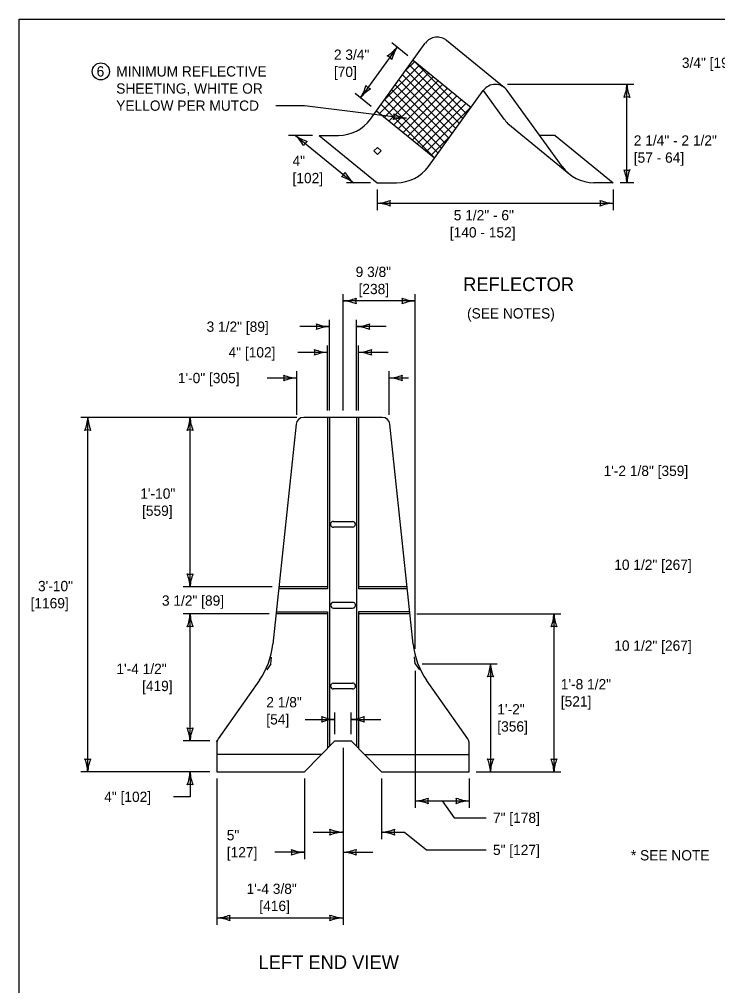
# Model space of a CAD drawing. Extents: x 49991.4 to 50021, y 49987.6 to 50011.4.
# Drawn here: x 49999.38 to 50003.46, y 49993.36 to 49999 of the extents above; entities that cross this region are included whole.
import ezdxf

# ---------------------------------------------------------------- set-up
doc = ezdxf.new("R2010")
doc.units = 0
for name, color, linetype in [('Level 1', 7, 'Continuous'), ('Level 2', 7, 'Continuous'), ('Level 3', 7, 'Continuous'), ('Level 4', 7, 'Continuous')]:
    doc.layers.add(name, color=color, linetype=linetype)

msp = doc.modelspace()

# ---------------------------------------------------------------- linework, layer by layer
at = {"layer": 'Level 1'}
for p, q in [((50002.218, 49998.5996), (50001.8793, 49998.8758)), ((50001.434, 49998.4163), (50001.7548, 49998.8598)), ((50001.6829, 49998.7604), (50001.9954, 49998.4479)), ((50001.6834, 49998.7611), (50002.0221, 49998.4849)), ((50001.4886, 49998.4503), (50001.7473, 49998.709)), ((50001.5094, 49998.5206), (50001.7201, 49998.7312)), ((50001.6389, 49998.6995), (50001.6928, 49998.7535)), ((50001.6413, 49998.7029), (50001.9538, 49998.3905)), ((50001.6621, 49998.7317), (50001.9746, 49998.4192)), ((50001.5159, 49998.428), (50001.7746, 49998.6868)), ((50001.5431, 49998.4058), (50001.8019, 49998.6645)), ((50001.5998, 49998.6455), (50001.9123, 49998.333)), ((50001.6206, 49998.6742), (50001.933, 49998.3617)), ((50001.5582, 49998.588), (50001.8707, 49998.2756)), ((50001.5704, 49998.3835), (50001.8291, 49998.6423)), ((50001.579, 49998.6168), (50001.8915, 49998.3043)), ((50001.5976, 49998.3613), (50001.8564, 49998.6201)), ((50001.6249, 49998.3391), (50001.8836, 49998.5978)), ((50001.5167, 49998.5306), (50001.8291, 49998.2181)), ((50001.5375, 49998.5593), (50001.8499, 49998.2469)), ((50001.6522, 49998.3168), (50001.9109, 49998.5756)), ((50001.6794, 49998.2946), (50001.9382, 49998.5533)), ((50001.7067, 49998.2724), (50001.9654, 49998.5311)), ((50001.7727, 49998.1401), (50002.0935, 49998.5835)), ((50002.2151, 49998.4163), (50002.0938, 49998.584)), ((50002.5538, 49998.1401), (50002.233, 49998.5835)), ((50001.4959, 49998.5019), (50001.8084, 49998.1894)), ((50001.734, 49998.2501), (50001.9927, 49998.5089)), ((50001.7612, 49998.2279), (50002.02, 49998.4866)), ((50001.4697, 49998.4657), (50001.8084, 49998.1894)), ((50002.2376, 49998.3898), (50002.6039, 49998.0896)), ((50001.1356, 49998.3213), (50001.2479, 49998.3213)), ((50001.1356, 49998.3213), (50001.4743, 49998.045)), ((50001.7885, 49998.2057), (50001.9029, 49998.3201)), ((50002.5135, 49998.3213), (50002.4227, 49998.3213)), ((50002.5135, 49998.3213), (50002.8522, 49998.045)), ((50001.4743, 49998.045), (50001.5866, 49998.045)), ((50002.8522, 49998.045), (50002.7399, 49998.045)), ((50001.5035, 49996.6742), (50001.0445, 49996.6742)), ((50001.184, 49996.6742), (50001.184, 49995.6732)), ((50001.1952, 49996.6742), (50001.1952, 49994.7528)), ((50001.3527, 49996.6742), (50001.3527, 49994.7528)), ((50001.364, 49996.6742), (50001.364, 49995.6732)), ((50000.9997, 49996.6339), (50000.8643, 49995.3498)), ((50001.6837, 49995.3498), (50001.5482, 49996.6339)), ((50001.2178, 49996.0665), (50001.3303, 49996.0665)), ((50001.3303, 49996.0332), (50001.2178, 49996.0332)), ((50001.184, 49995.6732), (50000.8984, 49995.6732)), ((50001.184, 49995.6844), (50000.8996, 49995.6844)), ((50001.6484, 49995.6844), (50001.364, 49995.6844)), ((50001.6496, 49995.6732), (50001.364, 49995.6732)), ((50000.8842, 49995.5382), (50001.184, 49995.5382)), ((50001.184, 49995.5382), (50001.184, 49994.7413)), ((50001.3303, 49995.594), (50001.2178, 49995.594)), ((50001.2178, 49995.5607), (50001.3303, 49995.5607)), ((50001.6638, 49995.5382), (50001.3642, 49995.5382)), ((50001.3642, 49995.5382), (50001.3642, 49994.7412)), ((50001.184, 49995.5269), (50000.883, 49995.5269)), ((50001.665, 49995.5268), (50001.3642, 49995.5268)), ((50000.7854, 49995.1389), (50000.5452, 49994.7958)), ((50001.2178, 49995.1215), (50001.3303, 49995.1215)), ((50001.3303, 49995.0884), (50001.2178, 49995.0884)), ((50002.0027, 49994.7958), (50001.7625, 49995.1389)), ((50000.5371, 49994.77), (50000.5371, 49994.6042)), ((50001.2262, 49994.7842), (50001.049, 49994.6042)), ((50001.2262, 49994.7842), (50001.3218, 49994.7842)), ((50001.3218, 49994.7842), (50001.499, 49994.6042)), ((50002.0109, 49994.6042), (50002.0109, 49994.77)), ((50000.5371, 49994.6042), (50001.049, 49994.6042)), ((50001.499, 49994.6042), (50002.0109, 49994.6042))]:
    msp.add_line(p, q, dxfattribs=at)
for points in [[(49999.3835, 49998.9992), (50016.7501, 49998.9992), (50016.7501, 49987.7988), (49999.3835, 49987.7988)], [(50001.4546, 49998.2302), (50001.4752, 49998.2095), (50001.4959, 49998.2302), (50001.4752, 49998.2508)]]:
    msp.add_lwpolyline(points, close=True, dxfattribs=at)
for centre, radius, start, end in [((50001.8246, 49998.8093), 0.0861, 50.5461, 144.119), ((50002.1632, 49998.5331), 0.0861, 35.881, 144.119), ((50001.2479, 49998.5509), 0.2297, 270, 324.119), ((50002.4012, 49998.5509), 0.2297, 215.881, 224.5527), ((50001.5866, 49998.2747), 0.2297, 270, 324.119), ((50002.7399, 49998.2747), 0.2297, 215.881, 270), ((50001.2177, 49996.0498), 0.0167, 89.8218, 270.1782), ((50001.3302, 49996.0498), 0.0167, 270.3209, 89.6791), ((50001.2178, 49995.5773), 0.0167, 90.1117, 269.8883), ((50001.3303, 49995.5773), 0.0167, 269.9135, 90.0865), ((50001.2178, 49995.1049), 0.0166, 90.0425, 269.9575), ((50001.3303, 49995.1049), 0.0166, 269.9732, 90.0268)]:
    msp.add_arc(centre, radius, start, end, dxfattribs=at)
for centre, major_axis, start_param, end_param in [((50001.0445, 49996.6292), (-0.045, 0), 4.712389, 6.178105), ((50001.5035, 49996.6292), (-0.045, 0), 3.246673, 4.712389), ((50000.4168, 49995.397), (0.45, 0), 5.672459, 6.178105), ((50002.1312, 49995.397), (-0.45, 0), 0.10508, 0.610726), ((50000.5821, 49994.77), (-0.045, 0), 5.672459, 6.283185), ((50001.9659, 49994.77), (0.045, 0), 0, 0.610726)]:
    msp.add_ellipse(centre, major_axis=major_axis, ratio=0.999982, start_param=start_param, end_param=end_param, dxfattribs=at)
at = {"layer": 'Level 2'}
msp.add_circle((49999.8595, 49998.6951), 0.05, dxfattribs=at)
at = {"layer": 'Level 3'}
for p, q in [((50001.5904, 49998.837), (50001.3767, 49998.5415)), ((50001.6524, 49998.7864), (50001.5594, 49998.8623)), ((50002.9722, 49998.6192), (50002.2339, 49998.6192)), ((50002.9322, 49998.045), (50002.9322, 49998.6192)), ((50001.4387, 49998.491), (50001.3457, 49998.5668)), ((50000.8812, 49998.4951), (50001.0492, 49998.4951)), ((50001.0492, 49998.4951), (50001.6448, 49998.4212)), ((50001.0956, 49998.3213), (50000.9556, 49998.3213)), ((50000.9956, 49998.3213), (50001.3343, 49998.045)), ((50001.4343, 49998.045), (50001.2943, 49998.045)), ((50002.9722, 49998.045), (50002.8922, 49998.045)), ((50001.4743, 49998.005), (50001.4743, 49997.885)), ((50002.8522, 49998.005), (50002.8522, 49997.885)), ((50001.4743, 49997.925), (50002.8522, 49997.925)), ((50001.274, 49996.7142), (50001.274, 49997.3942)), ((50001.6959, 49997.3542), (50001.274, 49997.3542)), ((50001.6959, 49995.323), (50001.6959, 49997.3942)), ((50001.1952, 49996.7142), (50001.1952, 49997.2442)), ((50001.3527, 49996.7142), (50001.3527, 49997.2442)), ((50001.1952, 49997.2042), (50001.0218, 49997.2042)), ((50001.5262, 49997.2042), (50001.3527, 49997.2042)), ((50001.184, 49996.7142), (50001.184, 49997.0942)), ((50001.364, 49996.7142), (50001.364, 49997.0942)), ((50001.184, 49997.0542), (50001.0105, 49997.0542)), ((50001.5374, 49997.0542), (50001.364, 49997.0542)), ((50001.004, 49996.9042), (50000.8305, 49996.9042)), ((50001.004, 49996.6888), (50001.004, 49996.9442)), ((50001.5439, 49996.689), (50001.544, 49996.9442)), ((50001.6559, 49996.9042), (50001.544, 49996.9042)), ((50001.0045, 49996.6742), (49999.7433, 49996.6742)), ((49999.7833, 49994.6042), (49999.7833, 49996.6742)), ((50000.3807, 49995.6844), (50000.3807, 49996.6742)), ((50000.8596, 49995.6844), (50000.3407, 49995.6844)), ((50000.843, 49995.5269), (50000.3407, 49995.5269)), ((50000.3807, 49994.7842), (50000.3807, 49995.5269)), ((50001.705, 49995.5268), (50002.546, 49995.5268)), ((50002.506, 49995.5268), (50002.506, 49994.6042)), ((50000.8521, 49995.2342), (50000.8562, 49995.2733)), ((50001.6959, 49995.2342), (50001.6914, 49995.2761)), ((50000.8521, 49995.2342), (50000.8285, 49995.2004)), ((50001.6959, 49995.2342), (50001.7202, 49995.1994)), ((50001.7359, 49995.2342), (50002.1752, 49995.2342)), ((50002.1352, 49995.2342), (50002.1352, 49994.6042)), ((50001.6959, 49995.1942), (50001.6959, 49994.3942)), ((50001.2262, 49994.8242), (50001.2262, 49994.9506)), ((50001.3218, 49994.8242), (50001.3218, 49994.9506)), ((50001.0527, 49994.9106), (50001.2262, 49994.9106)), ((50001.3218, 49994.9106), (50001.4952, 49994.9106)), ((50000.4971, 49994.7842), (50000.3407, 49994.7842)), ((50000.5385, 49994.7862), (50000.5371, 49994.7842)), ((50000.5371, 49994.7805), (50000.5371, 49994.7842)), ((50001.274, 49994.7442), (50001.274, 49993.7109)), ((50000.4971, 49994.6042), (49999.7433, 49994.6042)), ((50000.3807, 49994.6042), (50000.3807, 49994.4582)), ((50002.0509, 49994.6042), (50002.546, 49994.6042)), ((50000.5371, 49994.5642), (50000.5371, 49993.7109)), ((50001.049, 49994.5642), (50001.049, 49994.0942)), ((50001.499, 49994.5642), (50001.499, 49994.2117)), ((50002.0109, 49994.5642), (50002.0109, 49994.3942)), ((50000.3807, 49994.4582), (50000.2843, 49994.4582)), ((50001.6959, 49994.4342), (50002.0109, 49994.4342)), ((50001.1005, 49994.2517), (50001.274, 49994.2517)), ((50001.499, 49994.2517), (50001.634, 49994.2517)), ((50001.049, 49994.1342), (50000.8755, 49994.1342)), ((50001.274, 49994.1342), (50001.4474, 49994.1342)), ((50000.5371, 49993.7509), (50001.274, 49993.7509))]:
    msp.add_line(p, q, dxfattribs=at)
for points in [[(50001.8534, 49994.4342), (50001.9226, 49994.3355), (50002.1099, 49994.3355)], [(50001.634, 49994.2517), (50001.7618, 49994.1482), (50002.1099, 49994.1482)]]:
    msp.add_lwpolyline(points, dxfattribs=at)
for centre, radius, start, end in [((50001.4158, 49998.9746), 0.2223, 301.575, 321.7585), ((50001.7857, 49998.7099), 0.233, 146.9463, 166.1961), ((50001.5153, 49998.7331), 0.0548, 36.2578, 71.9801), ((50001.1814, 49998.6686), 0.233, 326.9463, 346.1961), ((50001.5513, 49998.4039), 0.2223, 121.575, 141.7585), ((50001.4519, 49998.6454), 0.0548, 216.2578, 251.9801), ((50002.7101, 49998.6283), 0.2223, 337.456, 357.6395), ((50003.1649, 49998.6307), 0.233, 182.8273, 202.0772), ((50002.9322, 49998.491), 0.0548, 72.1388, 107.8612), ((50001.5175, 49998.437), 0.0548, 335.061, 10.7833), ((50001.6275, 49998.1888), 0.233, 85.7494, 104.9993), ((50001.6812, 49998.6405), 0.2223, 240.3781, 260.5617), ((50000.8481, 49998.1549), 0.2223, 28.253, 48.4365), ((50001.1338, 49998.5089), 0.233, 233.6243, 252.8741), ((50001.095, 49998.2402), 0.0548, 122.9358, 158.6581), ((50001.2349, 49998.1261), 0.0548, 302.9358, 338.6581), ((50001.1961, 49997.8574), 0.233, 53.6243, 72.8741), ((50001.4818, 49998.2114), 0.2223, 208.253, 228.4365), ((50002.9322, 49998.1732), 0.0548, 252.1388, 287.8612), ((50002.6995, 49998.0335), 0.233, 2.8273, 22.0772), ((50003.1544, 49998.0359), 0.2223, 157.456, 177.6395), ((50001.4628, 49998.1577), 0.233, 272.8273, 292.0772), ((50001.4651, 49997.7029), 0.2223, 67.456, 87.6395), ((50001.6025, 49997.925), 0.0548, 162.1388, 197.8612), ((50002.8614, 49998.1472), 0.2223, 247.456, 267.6395), ((50002.724, 49997.925), 0.0548, 342.1388, 17.8612), ((50002.8637, 49997.6923), 0.233, 92.8273, 112.0772), ((50001.2625, 49997.5869), 0.233, 272.8273, 292.0772), ((50001.2648, 49997.132), 0.2223, 67.456, 87.6395), ((50001.4022, 49997.3542), 0.0548, 162.1388, 197.8612), ((50001.705, 49997.5763), 0.2223, 247.456, 267.6395), ((50001.5676, 49997.3542), 0.0548, 342.1388, 17.8612), ((50001.7074, 49997.1215), 0.233, 92.8273, 112.0772), ((50001.2044, 49997.4263), 0.2223, 247.456, 267.6395), ((50001.067, 49997.2042), 0.0548, 342.1388, 17.8612), ((50001.2067, 49996.9715), 0.233, 92.8273, 112.0772), ((50001.3412, 49997.4369), 0.233, 272.8273, 292.0772), ((50001.3436, 49996.982), 0.2223, 67.456, 87.6395), ((50001.481, 49997.2042), 0.0548, 162.1388, 197.8612), ((50001.1931, 49997.2763), 0.2223, 247.456, 267.6395), ((50001.0558, 49997.0542), 0.0548, 342.1388, 17.8612), ((50001.3525, 49997.2869), 0.233, 272.8273, 292.0772), ((50001.4922, 49997.0542), 0.0548, 162.1388, 197.8612), ((50001.1955, 49996.8215), 0.233, 92.8273, 112.0772), ((50001.3548, 49996.832), 0.2223, 67.456, 87.6395), ((50001.0131, 49997.1263), 0.2223, 247.456, 267.6395), ((50000.8758, 49996.9042), 0.0548, 342.1388, 17.8612), ((50001.0155, 49996.6715), 0.233, 92.8273, 112.0772), ((50001.5325, 49997.1369), 0.233, 272.8273, 292.0772), ((50001.5348, 49996.682), 0.2223, 67.456, 87.6395), ((50001.6722, 49996.9042), 0.0548, 162.1388, 197.8612), ((49999.5612, 49996.6834), 0.2223, 337.456, 357.6395), ((50000.016, 49996.6857), 0.233, 182.8273, 202.0772), ((50000.1586, 49996.6834), 0.2223, 337.456, 357.6395), ((50000.6134, 49996.6857), 0.233, 182.8273, 202.0772), ((49999.7833, 49996.546), 0.0548, 72.1388, 107.8612), ((50000.3807, 49996.546), 0.0548, 72.1388, 107.8612), ((50000.3807, 49995.8126), 0.0548, 252.1388, 287.8612), ((50000.148, 49995.6729), 0.233, 2.8273, 22.0772), ((50000.6029, 49995.6753), 0.2223, 157.456, 177.6395), ((50000.1586, 49995.5361), 0.2223, 337.456, 357.6395), ((50000.6134, 49995.5384), 0.233, 182.8273, 202.0772), ((50002.2838, 49995.536), 0.2223, 337.456, 357.6395), ((50002.7387, 49995.5383), 0.233, 182.8273, 202.0772), ((50000.3807, 49995.3987), 0.0548, 72.1388, 107.8612), ((50002.506, 49995.3986), 0.0548, 72.1388, 107.8612), ((50001.9131, 49995.2433), 0.2223, 337.456, 357.6395), ((50002.3679, 49995.2457), 0.233, 182.8273, 202.0772), ((50002.1352, 49995.106), 0.0548, 72.1388, 107.8612), ((50001.2353, 49995.1327), 0.2223, 247.456, 267.6395), ((50001.098, 49994.9106), 0.0548, 342.1388, 17.8612), ((50001.3103, 49995.1433), 0.233, 272.8273, 292.0772), ((50001.45, 49994.9106), 0.0548, 162.1388, 197.8612), ((50001.2377, 49994.6779), 0.233, 92.8273, 112.0772), ((50001.3126, 49994.6885), 0.2223, 67.456, 87.6395), ((50000.3807, 49994.9124), 0.0548, 252.1388, 287.8612), ((50000.148, 49994.7727), 0.233, 2.8273, 22.0772), ((50000.6029, 49994.775), 0.2223, 157.456, 177.6395), ((49999.7833, 49994.7324), 0.0548, 252.1388, 287.8612), ((49999.5506, 49994.5927), 0.233, 2.8273, 22.0772), ((50000.0054, 49994.595), 0.2223, 157.456, 177.6395), ((50002.1352, 49994.7324), 0.0548, 252.1388, 287.8612), ((50001.9025, 49994.5927), 0.233, 2.8273, 22.0772), ((50002.3573, 49994.595), 0.2223, 157.456, 177.6395), ((50002.506, 49994.7324), 0.0548, 252.1388, 287.8612), ((50002.2732, 49994.5927), 0.233, 2.8273, 22.0772), ((50002.7281, 49994.595), 0.2223, 157.456, 177.6395), ((50000.1586, 49994.6133), 0.2223, 337.456, 357.6395), ((50000.6134, 49994.6157), 0.233, 182.8273, 202.0772), ((50000.3807, 49994.476), 0.0548, 72.1388, 107.8612), ((50001.6844, 49994.6669), 0.233, 272.8273, 292.0772), ((50001.6867, 49994.2121), 0.2223, 67.456, 87.6395), ((50001.8241, 49994.4342), 0.0548, 162.1388, 197.8612), ((50002.02, 49994.6563), 0.2223, 247.456, 267.6395), ((50001.8826, 49994.4342), 0.0548, 342.1388, 17.8612), ((50002.0224, 49994.2015), 0.233, 92.8273, 112.0772), ((50001.2831, 49994.4738), 0.2223, 247.456, 267.6395), ((50001.1458, 49994.2517), 0.0548, 342.1388, 17.8612), ((50001.2855, 49994.019), 0.233, 92.8273, 112.0772), ((50001.4875, 49994.4844), 0.233, 272.8273, 292.0772), ((50001.4898, 49994.0296), 0.2223, 67.456, 87.6395), ((50001.6272, 49994.2517), 0.0548, 162.1388, 197.8612), ((50001.0581, 49994.3563), 0.2223, 247.456, 267.6395), ((50000.9208, 49994.1342), 0.0548, 342.1388, 17.8612), ((50001.0605, 49993.9015), 0.233, 92.8273, 112.0772), ((50001.2625, 49994.3669), 0.233, 272.8273, 292.0772), ((50001.2648, 49993.9121), 0.2223, 67.456, 87.6395), ((50001.4022, 49994.1342), 0.0548, 162.1388, 197.8612), ((50000.5256, 49993.9836), 0.233, 272.8273, 292.0772), ((50000.528, 49993.5288), 0.2223, 67.456, 87.6395), ((50000.6653, 49993.7509), 0.0548, 162.1388, 197.8612), ((50001.2831, 49993.9731), 0.2223, 247.456, 267.6395), ((50001.1458, 49993.7509), 0.0548, 342.1388, 17.8612), ((50001.2855, 49993.5182), 0.233, 92.8273, 112.0772)]:
    msp.add_arc(centre, radius, start, end, dxfattribs=at)
at = {"layer": 'Level 4'}
for p, q in [((50001.1487, 49994.7054), (50000.5371, 49994.7054)), ((50001.3993, 49994.7054), (50002.0109, 49994.7054))]:
    msp.add_line(p, q, dxfattribs=at)

# ---------------------------------------------------------------- texts
at = {"layer": 'Level 2'}
for s, height, p in [('2 3/4"', 0.06, (50001.2208, 49998.7627)), ('3/4" [19] DIA. BAR', 0.06, (50003.2532, 49998.7157)), ('6', 0.06, (49999.835, 49998.6651)), ('MINIMUM REFLECTIVE ', 0.06, (49999.9495, 49998.6651)), ('[70]', 0.06, (50001.2208, 49998.6627)), ('SHEETING, WHITE OR ', 0.06, (49999.9495, 49998.5651)), ('YELLOW PER MUTCD', 0.06, (49999.9495, 49998.4651)), ('2 1/4" - 2 1/2"', 0.06, (50002.9722, 49998.2616)), ('4"', 0.06, (50000.9791, 49998.1422)), ('[57 - 64]', 0.06, (50002.9722, 49998.1616)), ('[102]', 0.06, (50000.9791, 49998.0422)), ('5 1/2" - 6"', 0.06, (50001.9207, 49997.825)), ('[140 - 152]', 0.06, (50001.898, 49997.725)), ('9 3/8"', 0.06, (50001.3478, 49997.4942)), ('[238]', 0.06, (50001.3647, 49997.3942)), ('REFLECTOR', 0.08, (50001.9756, 49997.4118)), ('(SEE NOTES)', 0.06, (50001.9983, 49997.2518)), ('3 1/2" [89]', 0.06, (50000.4772, 49997.1742)), ('4" [102]', 0.06, (50000.6056, 49997.0242)), ('1\'-0" [305]', 0.06, (50000.3093, 49996.8742)), ('1\'-2 1/8" [359]', 0.06, (50002.7958, 49996.332)), ('1\'-10"', 0.06, (50000.0899, 49996.1993)), ('[559]', 0.06, (50000.1003, 49996.0993)), ('10 1/2" [267]', 0.06, (50002.8582, 49995.7836)), ('3\'-10"', 0.06, (49999.4925, 49995.6592)), ('[1169]', 0.06, (49999.449, 49995.5592)), ('3 1/2" [89]', 0.06, (50000.2164, 49995.5743)), ('10 1/2" [267]', 0.06, (50002.8582, 49995.3111)), ('1\'-4 1/2"', 0.06, (49999.9504, 49995.1756)), ('1\'-8 1/2"', 0.06, (50002.546, 49995.0856)), ('[419]', 0.06, (50000.1003, 49995.0756)), ('2 1/8"', 0.06, (50000.8262, 49994.9806)), ('[521]', 0.06, (50002.546, 49994.9856)), ('1\'-2"', 0.06, (50002.1752, 49994.9393)), ('[54]', 0.06, (50000.8262, 49994.8806)), ('[356]', 0.06, (50002.1752, 49994.8393)), ('4" [102]', 0.06, (49999.8793, 49994.4282)), ('7" [178]', 0.06, (50002.1499, 49994.3055)), ('5"', 0.06, (50000.5951, 49994.2042)), ('[127]', 0.06, (50000.5951, 49994.1042)), ('5" [127]', 0.06, (50002.1499, 49994.1182)), ('* SEE NOTE', 0.06, (50002.9554, 49994.0866)), ('1\'-4 3/8"', 0.06, (50000.7104, 49993.8909)), ('[416]', 0.06, (50000.7853, 49993.7909)), ('LEFT END VIEW', 0.08, (50000.7806, 49993.4522))]:
    msp.add_text(s, height=height, dxfattribs=at).set_placement(p)

doc.saveas('drawing.dxf')
